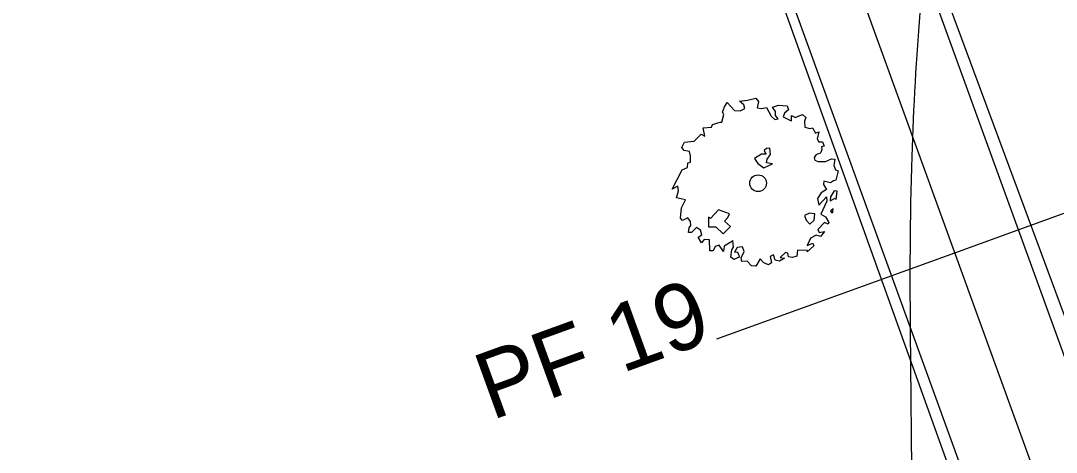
# Model space of a CAD drawing. Extents: x -475575 to -473225, y -1116053 to -1114104.
# Drawn here: x -474299.39 to -474268.69, y -1114859.77 to -1114846.97 of the extents above; entities that cross this region are included whole.
import ezdxf

# ---------------------------------------------------------------- set-up
doc = ezdxf.new("R2010")
doc.units = 0
for name, color, linetype in [('CESTN___P____KOP_N__VRH__Construction_', 7, 'Continuous'), ('IP', 7, 'Continuous'), ('POLYGONY_SITUACE_PF', 7, 'Continuous'), ('POLYGONY_SITUACE_PF_POPISY', 7, 'Continuous'), ('POLYGONY_SITUACE_PO', 7, 'Continuous'), ('Vrstevnice_vedlejsi', 7, 'Continuous')]:
    doc.layers.add(name, color=color, linetype=linetype)

msp = doc.modelspace()

# ---------------------------------------------------------------- linework, layer by layer
at = {"layer": 'CESTN___P____KOP_N__VRH__Construction_'}
for p, q in [((-474243.773, -1114922.437), (-474274.295, -1114839.898)), ((-474274.588, -1114840.004), (-474244.59, -1114922.733)), ((-474278.604, -1114841.46), (-474248.886, -1114924.291))]:
    msp.add_line(p, q, dxfattribs=at)
msp.add_lwpolyline([(-474278.348, -1114841.367), (-474248.351, -1114924.097)], dxfattribs=at)
at = {"layer": 'IP'}
for points in [[(-474275.558, -1114853.215), (-474275.672, -1114853.364), (-474275.801, -1114853.329), (-474275.977, -1114853.421), (-474276.073, -1114853.63), (-474275.902, -1114853.564), (-474275.878, -1114853.642), (-474276.072, -1114853.821), (-474276.06, -1114853.786), (-474276.356, -1114853.772), (-474276.377, -1114853.954), (-474276.506, -1114853.993), (-474276.624, -1114853.971), (-474276.649, -1114853.866), (-474276.719, -1114853.837), (-474276.872, -1114853.988), (-474276.748, -1114854.01), (-474276.891, -1114854.102), (-474277.025, -1114854.066), (-474277.075, -1114853.913), (-474277.169, -1114853.96), (-474277.127, -1114854.153), (-474277.221, -1114854.207), (-474277.357, -1114854.149), (-474277.47, -1114854.031), (-474277.599, -1114854.243), (-474277.721, -1114854.239), (-474277.851, -1114854.097), (-474278.006, -1114854.112), (-474278.03, -1114854.004), (-474277.938, -1114853.813), (-474277.987, -1114853.669), (-474278.146, -1114853.694), (-474278.23, -1114853.83), (-474278.146, -1114853.819), (-474278.109, -1114853.887), (-474278.09, -1114853.977), (-474278.243, -1114854.049), (-474278.332, -1114853.984), (-474278.302, -1114853.759), (-474278.252, -1114853.681), (-474278.279, -1114853.49), (-474278.286, -1114853.51), (-474278.535, -1114853.651), (-474278.557, -1114853.814), (-474278.679, -1114853.626), (-474278.8, -1114853.663), (-474278.856, -1114853.797), (-474278.954, -1114853.794), (-474278.97, -1114853.468), (-474279.13, -1114853.461), (-474279.207, -1114853.552), (-474279.301, -1114853.389), (-474279.2, -1114853.32), (-474279.232, -1114853.183), (-474279.355, -1114853.102), (-474279.503, -1114853.244), (-474279.59, -1114853.245), (-474279.57, -1114853.11), (-474279.524, -1114853.04), (-474279.529, -1114852.919), (-474279.612, -1114852.812), (-474279.771, -1114852.889), (-474279.832, -1114852.823), (-474279.799, -1114852.513), (-474279.677, -1114852.284), (-474279.947, -1114852.224), (-474279.892, -1114852.016), (-474279.909, -1114851.87), (-474280.077, -1114851.963), (-474279.778, -1114851.386), (-474279.616, -1114851.317), (-474279.61, -1114851.187), (-474279.535, -1114851.16), (-474279.531, -1114850.979), (-474279.558, -1114850.842), (-474279.715, -1114850.813), (-474279.785, -1114850.726), (-474279.705, -1114850.57), (-474279.421, -1114850.538), (-474279.219, -1114850.33), (-474279.108, -1114850.39), (-474279.152, -1114850.146), (-474278.907, -1114850.129), (-474278.88, -1114850.041), (-474278.656, -1114849.977), (-474278.603, -1114849.978), (-474278.54, -1114849.747), (-474278.579, -1114849.681), (-474278.52, -1114849.523), (-474278.44, -1114849.397), (-474278.23, -1114849.633), (-474278.063, -1114849.639), (-474277.92, -1114849.571), (-474277.955, -1114849.462), (-474278.083, -1114849.355), (-474277.844, -1114849.325), (-474277.597, -1114849.265), (-474277.511, -1114849.362), (-474277.551, -1114849.551), (-474277.428, -1114849.57), (-474277.277, -1114849.538), (-474277.144, -1114849.796), (-474277.03, -1114849.893), (-474276.935, -1114849.876), (-474277.012, -1114849.778), (-474277.012, -1114849.664), (-474277.097, -1114849.529), (-474276.922, -1114849.475), (-474276.669, -1114849.49), (-474276.621, -1114849.61), (-474276.742, -1114849.713), (-474276.782, -1114849.822), (-474276.571, -1114849.924), (-474276.535, -1114849.934), (-474276.533, -1114849.779), (-474276.415, -1114849.838), (-474276.342, -1114849.793), (-474276.212, -1114849.75), (-474276.11, -1114849.84), (-474276.154, -1114849.943), (-474276.137, -1114850.121), (-474275.998, -1114850.166), (-474275.913, -1114850.148), (-474275.825, -1114850.306), (-474275.731, -1114850.265), (-474275.774, -1114850.47), (-474275.722, -1114850.562), (-474275.618, -1114850.557), (-474275.573, -1114850.692), (-474275.643, -1114850.706), (-474275.637, -1114850.788), (-474275.663, -1114850.875), (-474275.701, -1114850.91), (-474275.768, -1114850.924), (-474275.828, -1114850.967), (-474275.869, -1114851.021), (-474275.845, -1114851.104), (-474275.746, -1114851.141), (-474275.525, -1114851.141), (-474275.355, -1114851.068), (-474275.251, -1114851.077), (-474275.281, -1114851.259), (-474275.236, -1114851.389), (-474275.158, -1114851.42), (-474275.22, -1114851.693), (-474275.288, -1114851.715), (-474275.383, -1114851.777), (-474275.58, -1114851.722), (-474275.588, -1114851.82), (-474275.5, -1114851.976), (-474275.658, -1114852.074), (-474275.768, -1114852.24), (-474275.725, -1114852.442), (-474275.502, -1114852.188), (-474275.49, -1114852.323), (-474275.667, -1114852.7), (-474275.532, -1114852.782), (-474275.432, -1114852.951), (-474275.453, -1114852.997), (-474275.556, -1114852.948), (-474275.76, -1114853.156), (-474275.716, -1114853.252)], [(-474277.287, -1114850.923), (-474277.43, -1114850.923), (-474277.632, -1114851.052), (-474277.535, -1114851.203), (-474277.36, -1114851.331), (-474277.1, -1114851.209), (-474277.276, -1114851.178), (-474277.258, -1114851.075), (-474277.188, -1114850.979), (-474277.158, -1114850.938), (-474277.18, -1114850.75), (-474277.275, -1114850.761), (-474277.351, -1114850.812), (-474277.321, -1114850.884)], [(-474275.267, -1114852.017), (-474275.379, -1114852.194), (-474275.394, -1114852.309), (-474275.24, -1114852.235), (-474275.216, -1114852.267), (-474275.181, -1114852.02)], [(-474275.3, -1114852.542), (-474275.379, -1114852.618), (-474275.341, -1114852.666), (-474275.307, -1114852.642)], [(-474278.371, -1114852.691), (-474278.699, -1114852.578), (-474278.94, -1114852.838), (-474278.993, -1114852.789), (-474279, -1114853.079), (-474278.78, -1114853.084), (-474278.558, -1114853.293), (-474278.35, -1114853.071), (-474278.519, -1114852.912), (-474278.421, -1114852.808)], [(-474275.847, -1114852.698), (-474276.004, -1114852.672), (-474276.154, -1114852.749), (-474276.102, -1114852.887), (-474275.998, -1114852.997), (-474275.861, -1114852.883)]]:
    msp.add_lwpolyline(points, close=True, dxfattribs=at)
msp.add_circle((-474277.527, -1114851.786), 0.247, dxfattribs=at)
at = {"layer": 'POLYGONY_SITUACE_PF'}
msp.add_lwpolyline([(-474278.747, -1114856.404), (-474271.696, -1114853.847), (-474264.645, -1114851.291)], dxfattribs=at)
at = {"layer": 'POLYGONY_SITUACE_PO'}
msp.add_lwpolyline([(-474033.93, -1115484.017), (-474028.81, -1115469.55), (-474027.706, -1115465.586), (-474027.155, -1115461.509), (-474027.167, -1115457.394), (-474027.702, -1115449.947), (-474028.133, -1115446.706), (-474028.952, -1115443.542), (-474030.148, -1115440.499), (-474155.776, -1115170.193), (-474159.336, -1115162.232), (-474162.663, -1115154.172), (-474165.754, -1115146.018), (-474287.504, -1114810.25), (-474291.915, -1114795.876)], dxfattribs=at)
at = {"layer": 'Vrstevnice_vedlejsi'}
for points in [[(-474198.341, -1114669.49), (-474196.681, -1114672.256), (-474195.18, -1114674.653), (-474193.836, -1114676.681), (-474192.651, -1114678.341), (-474192.443, -1114683.526), (-474193.214, -1114692.237), (-474194.962, -1114704.473), (-474196.31, -1114712.997), (-474197.258, -1114717.807), (-474197.807, -1114718.903), (-474198.355, -1114720.033), (-474198.903, -1114721.196), (-474199.452, -1114722.393), (-474202.29, -1114724.764), (-474207.417, -1114728.309), (-474214.834, -1114733.029), (-474221.352, -1114738.648), (-474226.971, -1114745.166), (-474231.691, -1114752.583), (-474235.037, -1114757.727), (-474237.009, -1114760.598), (-474237.607, -1114761.196), (-474238.205, -1114762.022), (-474238.804, -1114763.076), (-474239.402, -1114764.358), (-474242.028, -1114769.031), (-474246.681, -1114777.093), (-474253.362, -1114788.547), (-474258.559, -1114799.152), (-474262.27, -1114808.908), (-474264.497, -1114817.816), (-474266.676, -1114825.23), (-474268.807, -1114831.15), (-474270.889, -1114835.575), (-474272.278, -1114842.188), (-474272.972, -1114850.991), (-474272.972, -1114861.981), (-474273.054, -1114870.089), (-474273.218, -1114875.314), (-474273.465, -1114877.657), (-474273.273, -1114882.608), (-474272.641, -1114890.167), (-474271.571, -1114900.334), (-474271.061, -1114908.167), (-474271.11, -1114913.667), (-474271.719, -1114916.834), (-474271.646, -1114922.058), (-474270.891, -1114929.339), (-474269.454, -1114938.678), (-474268.091, -1114946.236), (-474266.802, -1114952.012), (-474265.586, -1114956.006), (-474264.292, -1114960.893), (-474262.92, -1114966.673), (-474261.469, -1114973.346), (-474259.897, -1114980.014), (-474258.202, -1114986.679), (-474256.386, -1114993.34), (-474254.916, -1115000.31), (-474253.793, -1115007.591), (-474253.017, -1115015.182), (-474252.121, -1115021.507), (-474251.104, -1115026.568), (-474249.968, -1115030.364), (-474249.22, -1115033.873), (-474248.86, -1115037.095), (-474248.889, -1115040.031), (-474248.926, -1115042.279), (-474248.97, -1115043.838), (-474249.022, -1115044.709), (-474249.185, -1115045.346), (-474249.46, -1115045.75), (-474249.845, -1115045.92), (-474250.053, -1115046.628), (-474250.085, -1115047.873), (-474249.939, -1115049.656), (-474250.24, -1115054.341), (-474250.987, -1115061.928), (-474252.18, -1115072.418), (-474252.552, -1115080.569), (-474252.103, -1115086.383), (-474250.833, -1115089.859), (-474248.888, -1115093.001), (-474246.267, -1115095.808), (-474242.971, -1115098.281), (-474237.53, -1115101.018), (-474229.942, -1115104.018), (-474220.207, -1115107.282), (-474212.554, -1115110.016), (-474206.982, -1115112.221), (-474203.491, -1115113.895), (-474200.507, -1115114.848), (-474198.031, -1115115.078), (-474196.062, -1115114.586), (-474193.634, -1115114.914), (-474190.746, -1115116.062)], [(-474227.218, -1115164.851), (-474226.448, -1115162.426), (-474227.525, -1115159.571), (-474230.451, -1115156.287), (-474235.226, -1115152.573), (-474240.399, -1115148.881), (-474245.971, -1115145.211), (-474251.942, -1115141.562), (-474256.818, -1115137.139), (-474260.6, -1115131.942), (-474263.287, -1115125.971), (-474265.918, -1115121.36), (-474268.492, -1115118.11), (-474271.011, -1115116.221), (-474273.409, -1115112.993), (-474275.686, -1115108.429), (-474277.843, -1115102.526), (-474279.974, -1115096.744), (-474282.078, -1115091.082), (-474284.156, -1115085.541), (-474285.812, -1115080.883), (-474287.047, -1115077.109), (-474287.86, -1115074.218), (-474288.244, -1115068.81), (-474288.198, -1115060.885), (-474287.724, -1115050.442), (-474287.488, -1115042.595), (-474287.491, -1115037.342), (-474287.732, -1115034.684), (-474288.91, -1115029.354), (-474291.024, -1115021.351), (-474294.074, -1115010.675), (-474297.009, -1115000.754), (-474299.828, -1114991.588), (-474302.532, -1114983.176), (-474304.676, -1114975.928), (-474306.261, -1114969.843), (-474307.286, -1114964.921), (-474309.265, -1114957.199), (-474312.198, -1114946.677), (-474316.084, -1114933.354), (-474318.675, -1114924.468), (-474319.971, -1114920.02), (-474319.973, -1114920.01), (-474319.977, -1114919.992), (-474319.984, -1114919.965), (-474319.992, -1114919.931), (-474321.301, -1114916.779), (-474323.911, -1114910.509), (-474327.823, -1114901.121), (-474333.571, -1114893.897), (-474341.156, -1114888.835), (-474350.578, -1114885.936), (-474361.246, -1114883.666), (-474373.16, -1114882.025), (-474386.32, -1114881.012), (-474395.152, -1114880.336), (-474399.654, -1114879.994), (-474399.827, -1114879.989), (-474403.877, -1114879.477), (-474411.805, -1114878.46), (-474423.609, -1114876.937), (-474431.988, -1114875.62), (-474436.942, -1114874.51), (-474438.471, -1114873.607), (-474443.932, -1114869.371), (-474453.324, -1114861.802), (-474466.647, -1114850.901), (-474475.533, -1114843.63), (-474479.981, -1114839.989), (-474479.99, -1114839.978), (-474480.008, -1114839.975), (-474480.035, -1114839.978), (-474480.069, -1114839.989), (-474480.092, -1114840.008), (-474480.104, -1114840.035), (-474480.104, -1114840.069), (-474483.152, -1114844.525), (-474489.247, -1114853.403), (-474498.39, -1114866.701), (-474505.505, -1114879.646), (-474510.592, -1114892.237), (-474513.651, -1114904.473), (-474515.798, -1114912.997), (-474517.033, -1114917.807), (-474517.355, -1114918.903), (-474517.71, -1114919.879), (-474518.097, -1114920.733), (-474518.517, -1114921.467), (-474518.841, -1114922.054), (-474519.069, -1114922.494), (-474519.202, -1114922.788), (-474519.513, -1114923.611), (-474520.002, -1114924.961), (-474520.669, -1114926.839), (-474521.912, -1114930.34), (-474523.73, -1114935.464)]]:
    msp.add_spline(points, degree=3, dxfattribs=at)

# ---------------------------------------------------------------- texts
at = {"layer": 'POLYGONY_SITUACE_PF_POPISY'}
msp.add_text('PF 19', height=1.9765, rotation=19.9307, dxfattribs=at).set_placement((-474285.436, -1114858.829))

doc.saveas('drawing.dxf')
